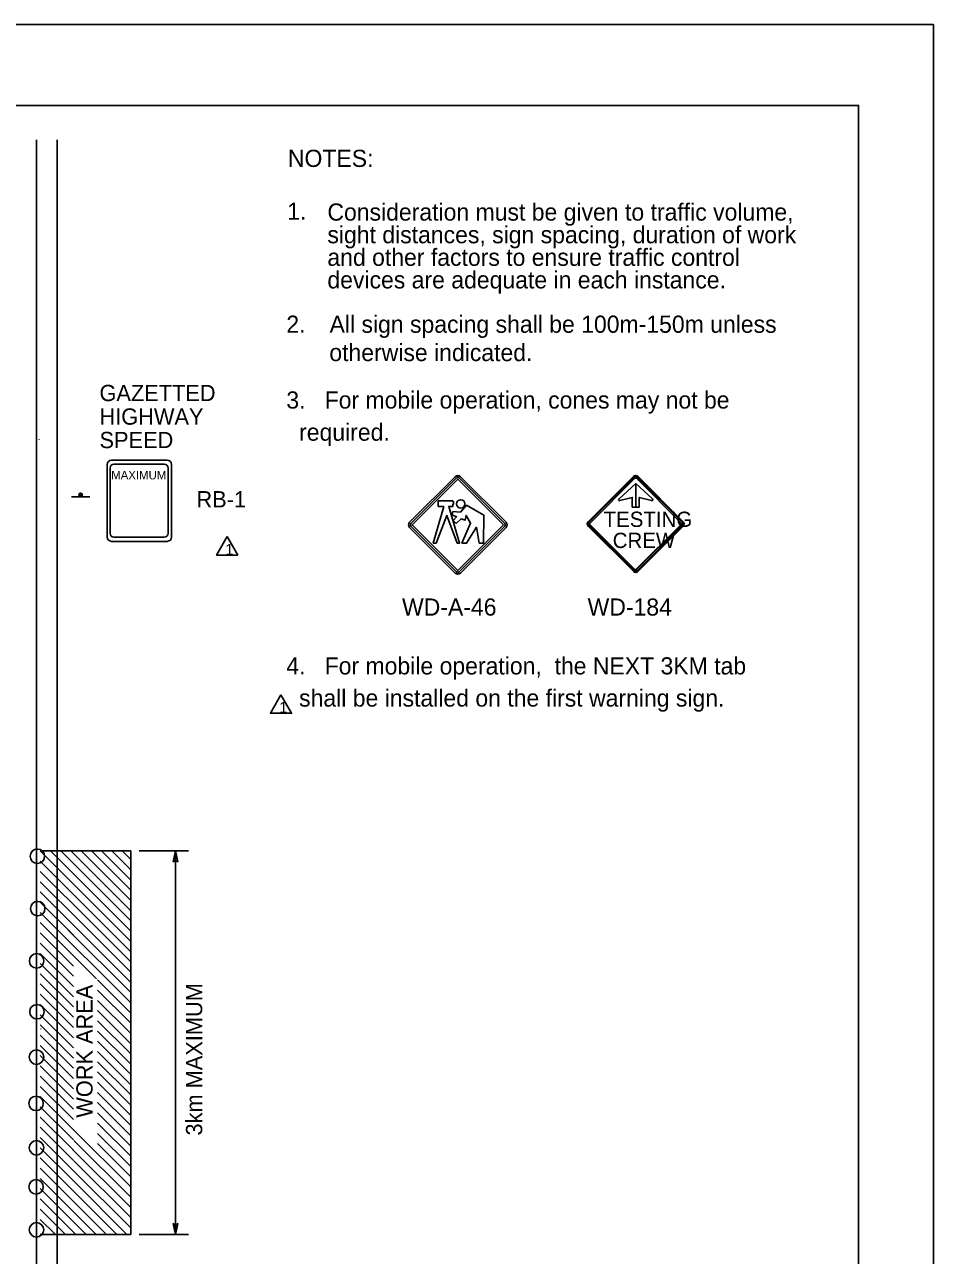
# Model space of a CAD drawing. Extents: x 1371 to 1587, y 163 to 442.
# Drawn here: x 1465.4 to 1587, y 277.8 to 442.4 of the extents above; entities that cross this region are included whole.
import ezdxf

# ---------------------------------------------------------------- set-up
doc = ezdxf.new("R2010")
doc.units = 0
for name, color, linetype in [('Level 1', 7, 'Continuous'), ('Level 10', 7, 'Continuous'), ('Level 2', 7, 'Continuous'), ('Level 3', 7, 'Continuous'), ('Level 44', 7, 'Continuous'), ('Level 60', 7, 'Continuous'), ('Level 61', 7, 'Continuous'), ('Level 62', 7, 'Continuous')]:
    doc.layers.add(name, color=color, linetype=linetype)

msp = doc.modelspace()

# ---------------------------------------------------------------- linework, layer by layer
at = {"layer": 'Level 1'}
for p, q in [((1516.91, 375.86), (1523.01, 381.96)), ((1523.3, 382.27), (1523.3, 382.27)), ((1523.35, 382.3), (1523.35, 382.3)), ((1523.7, 381.96), (1529.8, 375.86)), ((1540.78, 375.93), (1546.87, 382.01)), ((1547.43, 382.01), (1553.51, 375.93)), ((1517.08, 375.69), (1523.18, 381.79)), ((1517.25, 375.52), (1523.35, 381.62)), ((1523.36, 381.62), (1529.46, 375.52)), ((1523.53, 381.79), (1529.63, 375.69)), ((1546.98, 381.9), (1540.89, 375.82)), ((1540.89, 375.82), (1546.98, 381.9)), ((1541, 375.7), (1547.09, 381.79)), ((1547.14, 381.03), (1547.14, 377.9)), ((1547.21, 381.79), (1553.28, 375.7)), ((1523.18, 369.23), (1517.08, 375.34)), ((1523.35, 369.4), (1517.25, 375.51)), ((1523.31, 375.4), (1523.31, 375.4)), ((1529.46, 375.51), (1523.36, 369.4)), ((1529.63, 375.34), (1523.53, 369.23)), ((1540.5, 375.65), (1540.5, 375.65)), ((1546.87, 369.28), (1540.78, 375.36)), ((1547.09, 369.5), (1541, 375.58)), ((1547.17, 369.54), (1553.25, 375.62)), ((1547.17, 369.54), (1553.25, 375.62)), ((1547.17, 369.54), (1553.25, 375.62)), ((1553.25, 375.62), (1547.17, 369.54)), ((1553.28, 375.58), (1547.21, 369.5)), ((1553.51, 375.36), (1547.43, 369.28)), ((1553.79, 375.64), (1553.79, 375.64)), ((1523.01, 369.06), (1516.91, 375.17)), ((1529.8, 375.17), (1523.7, 369.06)), ((1472.72, 330.85), (1472.72, 330.85))]:
    msp.add_line(p, q, dxfattribs=at)
for points in [[(1521.49, 377.99), (1520.74, 377.99), (1520.74, 378.71), (1522.7, 378.71), (1522.7, 378.61), (1522.78, 378.61), (1522.78, 378.32), (1522.7, 378.32), (1522.7, 377.99), (1522.15, 377.99), (1523.59, 373.08), (1523.28, 373.08), (1521.87, 376.79), (1520.46, 373.08), (1520.07, 373.08)], [(1521.49, 377.99), (1520.74, 377.99), (1520.74, 378.71), (1522.7, 378.71), (1522.7, 378.61), (1522.78, 378.61), (1522.78, 378.32), (1522.7, 378.32), (1522.7, 377.99), (1522.15, 377.99), (1523.59, 373.08), (1523.28, 373.08), (1521.87, 376.79), (1520.46, 373.08), (1520.07, 373.08)], [(1522.67, 377.31), (1523.7, 377.22), (1524.52, 378.15), (1526.85, 376.8), (1526.77, 373.08), (1526.22, 373.08), (1525.87, 375.21), (1524.52, 373.08), (1523.9, 373.08), (1525.07, 375.73), (1524.45, 376.79), (1524.33, 376.13), (1523.79, 376.34), (1523.14, 375.72), (1522.74, 376.09), (1523.18, 376.61), (1522.58, 376.88)], [(1522.67, 377.31), (1523.7, 377.22), (1524.52, 378.15), (1526.85, 376.8), (1526.77, 373.08), (1526.22, 373.08), (1525.87, 375.21), (1524.52, 373.08), (1523.9, 373.08), (1525.07, 375.73), (1524.45, 376.79), (1524.33, 376.13), (1523.79, 376.34), (1523.14, 375.72), (1522.74, 376.09), (1523.18, 376.61), (1522.58, 376.88)], [(1492.5, 373.94), (1491.08, 371.47), (1493.92, 371.47)], [(1499.7, 352.8), (1498.28, 350.33), (1501.12, 350.33)]]:
    msp.add_lwpolyline(points, close=True, dxfattribs=at)
for centre, radius, start, end in [((1523.35, 381.61), 0.487, 45.0349, 135), ((1547.15, 381.73), 0.398, 44.9995, 135.0002), ((1547.15, 381.73), 0.241, 44.9995, 135.0002), ((1547.15, 381.73), 0.241, 44.9995, 135.0002), ((1523.35, 381.61), 0.247, 45.0349, 135), ((1523.35, 381.61), 0.00743, 45.0349, 135), ((1547.15, 381.73), 0.0846, 44.9995, 135.0002), ((1547.15, 381.73), 0.0324, 45, 135), ((1547.15, 381.73), 0.0324, 45, 135), ((1547.15, 381.73), 0.0324, 45, 135), ((1517.25, 375.52), 0.487, 135, 224.9651), ((1517.25, 375.52), 0.247, 135, 224.9651), ((1517.25, 375.52), 0.00743, 135, 224.9651), ((1529.46, 375.52), 0.00743, 315, 45.0346), ((1529.46, 375.52), 0.247, 315, 45.0346), ((1529.46, 375.52), 0.487, 315, 45.0346), ((1541.06, 375.64), 0.398, 135.0005, 225), ((1541.06, 375.64), 0.241, 135.0005, 225), ((1541.06, 375.64), 0.241, 135.0005, 225), ((1541.06, 375.64), 0.241, 135.0005, 225), ((1541.06, 375.64), 0.0846, 135.0005, 225), ((1553.23, 375.64), 0.0324, 315, 45), ((1553.23, 375.64), 0.0324, 315, 45), ((1553.23, 375.64), 0.0324, 315, 45), ((1553.23, 375.64), 0.0846, 315.0005, 44.9999), ((1553.23, 375.64), 0.241, 315.0005, 44.9999), ((1553.23, 375.64), 0.241, 315.0005, 44.9999), ((1553.23, 375.64), 0.398, 315.0005, 44.9999), ((1523.35, 369.41), 0.487, 224.965, 315), ((1523.35, 369.41), 0.247, 224.965, 315), ((1523.35, 369.41), 0.00743, 224.965, 315), ((1547.15, 369.56), 0.398, 224.9995, 315), ((1547.15, 369.56), 0.0846, 224.9995, 315), ((1547.15, 369.56), 0.0324, 225, 315), ((1547.15, 369.56), 0.0324, 225, 315), ((1547.15, 369.56), 0.0324, 225, 315)]:
    msp.add_arc(centre, radius, start, end, dxfattribs=at)
at = {"layer": 'Level 10'}
for p, q in [((1467.02, 427.01), (1467.02, 182.32)), ((1469.76, 427.01), (1469.76, 182.32)), ((1467.36, 386.96), (1467.37, 386.95)), ((1467.51, 331.9), (1479.6, 331.9)), ((1467.51, 331.9), (1479.6, 319.8)), ((1467.51, 331.9), (1479.6, 331.9)), ((1468.87, 331.9), (1479.6, 321.17)), ((1470.24, 331.9), (1479.6, 322.54)), ((1471.61, 331.9), (1479.6, 323.91)), ((1472.98, 331.9), (1479.6, 325.28)), ((1474.35, 331.9), (1479.6, 326.64)), ((1475.71, 331.9), (1479.6, 328.01)), ((1477.08, 331.9), (1479.6, 329.38)), ((1478.45, 331.9), (1479.6, 330.75)), ((1479.6, 331.9), (1479.6, 280.61)), ((1480.75, 331.9), (1487.33, 331.9)), ((1485.6, 280.62), (1485.6, 331.9)), ((1467.51, 330.53), (1479.6, 318.43)), ((1467.51, 329.16), (1474.26, 322.41)), ((1467.51, 327.79), (1472.89, 322.41)), ((1467.51, 326.42), (1471.94, 321.99)), ((1467.51, 325.06), (1471.94, 320.62)), ((1467.5, 323.69), (1479.6, 311.59)), ((1467.51, 322.32), (1475.01, 314.81)), ((1471.26, 321.3), (1479.6, 312.96)), ((1471.94, 321.99), (1479.6, 314.33)), ((1472.89, 322.41), (1479.6, 315.7)), ((1474.26, 322.41), (1479.6, 317.06)), ((1467.51, 320.95), (1471.94, 316.51)), ((1467.51, 319.58), (1471.94, 315.14)), ((1467.51, 318.21), (1471.94, 313.78)), ((1467.51, 316.85), (1471.94, 312.41)), ((1467.51, 315.48), (1471.94, 311.04)), ((1475.17, 314.66), (1479.6, 310.22)), ((1467.51, 314.11), (1471.94, 309.67)), ((1475.17, 313.29), (1479.6, 308.85)), ((1467.51, 312.74), (1471.94, 308.3)), ((1467.51, 311.37), (1471.94, 306.93)), ((1475.17, 311.92), (1479.6, 307.49)), ((1467.51, 310), (1471.94, 305.56)), ((1475.17, 310.55), (1479.6, 306.12)), ((1467.51, 308.63), (1471.94, 304.2)), ((1467.58, 308.1), (1467.59, 308.09)), ((1475.17, 309.18), (1479.6, 304.75)), ((1467.51, 307.26), (1471.94, 302.83)), ((1475.17, 307.81), (1479.6, 303.38)), ((1475.17, 306.45), (1479.6, 302.01)), ((1467.51, 305.9), (1471.94, 301.46)), ((1475.17, 305.08), (1479.6, 300.64)), ((1467.51, 304.53), (1471.94, 300.09)), ((1467.51, 303.16), (1471.94, 298.72)), ((1475.17, 303.71), (1479.6, 299.28)), ((1467.51, 301.79), (1471.94, 297.35)), ((1475.17, 302.34), (1479.6, 297.91)), ((1467.51, 300.42), (1471.94, 295.99)), ((1475.17, 300.97), (1479.6, 296.54)), ((1475.17, 299.6), (1479.6, 295.17)), ((1467.51, 299.06), (1471.94, 294.62)), ((1475.17, 298.24), (1479.6, 293.8)), ((1467.51, 297.69), (1471.94, 293.25)), ((1467.51, 296.32), (1471.94, 291.88)), ((1475.17, 296.87), (1479.6, 292.43)), ((1467.51, 294.95), (1471.94, 290.51)), ((1471.9, 294.66), (1479.6, 286.96)), ((1475.17, 295.5), (1479.6, 291.07)), ((1467.51, 293.58), (1471.94, 289.14)), ((1472.02, 293.17), (1479.6, 285.59)), ((1475.17, 294.13), (1479.6, 289.7)), ((1467.51, 292.21), (1471.94, 287.78)), ((1471.87, 291.95), (1479.6, 284.22)), ((1475.17, 292.76), (1479.6, 288.33)), ((1467.51, 290.85), (1477.74, 280.61)), ((1472.01, 290.44), (1479.6, 282.86)), ((1467.51, 289.48), (1476.37, 280.61)), ((1467.51, 288.11), (1475, 280.61)), ((1471.95, 289.13), (1479.6, 281.49)), ((1467.51, 286.74), (1473.63, 280.61)), ((1471.94, 287.78), (1479.1, 280.61)), ((1467.51, 285.37), (1472.26, 280.61)), ((1467.51, 284), (1470.89, 280.61)), ((1467.51, 282.63), (1469.53, 280.61)), ((1467.5, 280.61), (1479.6, 280.61)), ((1480.75, 280.62), (1487.33, 280.62))]:
    msp.add_line(p, q, dxfattribs=at)
for points in [[(1485.6, 331.9), (1485.9, 330.45), (1485.6, 330.69), (1485.3, 330.45)], [(1485.6, 280.62), (1485.3, 282.07), (1485.6, 281.83), (1485.9, 282.07)]]:
    msp.add_lwpolyline(points, close=True, dxfattribs=at)
for centre in [(1467.12, 331.19), (1467.17, 324.19), (1467.02, 317.2), (1467.07, 310.4), (1467, 304.33), (1466.95, 298.14), (1467, 292.2), (1466.95, 286.98), (1467, 281.23)]:
    msp.add_circle(centre, 0.968, dxfattribs=at)
at = {"layer": 'Level 2'}
for centre, radius, start, end in [((1547.15, 381.73), 0.398, 44.9995, 135.0002), ((1547.15, 381.73), 0.241, 44.9995, 135.0002), ((1541.06, 375.64), 0.398, 135.0005, 225), ((1553.23, 375.64), 0.241, 315.0005, 44.9999), ((1553.23, 375.64), 0.398, 315.0005, 44.9999), ((1547.15, 369.56), 0.241, 224.9995, 315)]:
    msp.add_arc(centre, radius, start, end, dxfattribs=at)
at = {"layer": 'Level 3'}
for centre, start, end in [((1547.15, 381.73), 45, 135), ((1547.15, 381.73), 45, 135), ((1553.23, 375.64), 315, 45), ((1553.23, 375.64), 315, 45), ((1547.15, 369.56), 225, 315), ((1547.15, 369.56), 225, 315)]:
    msp.add_arc(centre, 0.0324, start, end, dxfattribs=at)
at = {"layer": 'Level 44'}
for p, q in [((1476.47, 373.89), (1476.47, 383.6)), ((1477.05, 384.18), (1484.5, 384.18)), ((1477.37, 383.64), (1484.08, 383.64)), ((1485.07, 383.6), (1485.07, 373.89)), ((1476.86, 374.38), (1476.86, 383.12)), ((1484.6, 383.12), (1484.6, 374.38)), ((1471.7, 379.25), (1474.12, 379.25)), ((1476.47, 373.89), (1476.47, 373.89)), ((1476.86, 374.38), (1476.86, 374.38)), ((1477.09, 373.81), (1477.09, 373.81)), ((1484.08, 373.87), (1477.37, 373.87)), ((1484.5, 373.31), (1477.05, 373.31)), ((1477.18, 373.56), (1477.18, 373.56))]:
    msp.add_line(p, q, dxfattribs=at)
for centre, radius in [((1472.91, 379.52), 0.242), ((1472.91, 379.52), 0.121), ((1523.74, 378.32), 0.56), ((1523.74, 378.32), 0.56)]:
    msp.add_circle(centre, radius, dxfattribs=at)
for centre, radius, start, end in [((1477.05, 383.6), 0.575, 90, 180), ((1477.37, 383.12), 0.517, 90, 180), ((1484.08, 383.12), 0.517, 360, 90), ((1484.5, 383.6), 0.575, 360, 90), ((1477.05, 373.89), 0.575, 180, 270), ((1477.37, 374.38), 0.517, 180, 270), ((1484.08, 374.38), 0.517, 270, 360), ((1484.5, 373.89), 0.575, 270, 360)]:
    msp.add_arc(centre, radius, start, end, dxfattribs=at)
at = {"layer": 'Level 60'}
msp.add_line((1545.03, 378.76), (1545.03, 378.76), dxfattribs=at)
for points in [[(1370.95, 442.43), (1586.95, 442.43), (1586.95, 163.43), (1370.95, 163.43)], [(1390.08, 431.62), (1576.95, 431.62), (1576.95, 174.24), (1390.08, 174.24)]]:
    msp.add_lwpolyline(points, close=True, dxfattribs=at)
for points in [[(1544.91, 378.99), (1547.14, 381.03), (1549.38, 378.99)], [(1549.25, 378.76), (1547.61, 379.18), (1547.61, 377.9), (1546.68, 377.9), (1546.68, 379.18), (1545.03, 378.76)]]:
    msp.add_lwpolyline(points, dxfattribs=at)
for centre, start, end in [((1545, 378.89), 132.3048, 284.4075), ((1549.29, 378.89), 255.5925, 47.6952)]:
    msp.add_arc(centre, 0.14, start, end, dxfattribs=at)
at = {"layer": 'Level 61'}
msp.add_line((1545.03, 378.76), (1545.03, 378.76), dxfattribs=at)
for points in [[(1544.91, 378.99), (1547.14, 381.03), (1549.38, 378.99)], [(1549.25, 378.76), (1547.61, 379.18), (1547.61, 377.9), (1546.68, 377.9), (1546.68, 379.18), (1545.03, 378.76)]]:
    msp.add_lwpolyline(points, dxfattribs=at)
for centre, start, end in [((1545, 378.89), 132.3048, 284.4075), ((1549.29, 378.89), 255.5925, 47.6952)]:
    msp.add_arc(centre, 0.14, start, end, dxfattribs=at)
at = {"layer": 'Level 62'}
for p, q in [((1540.89, 375.82), (1546.98, 381.9)), ((1547.32, 381.9), (1553.4, 375.82)), ((1545.03, 378.76), (1545.03, 378.76)), ((1546.98, 369.39), (1540.89, 375.47)), ((1553.4, 375.47), (1547.32, 369.39))]:
    msp.add_line(p, q, dxfattribs=at)
for points in [[(1544.91, 378.99), (1547.14, 381.03), (1549.38, 378.99)], [(1549.25, 378.76), (1547.61, 379.18), (1547.61, 377.9), (1546.68, 377.9), (1546.68, 379.18), (1545.03, 378.76)]]:
    msp.add_lwpolyline(points, dxfattribs=at)
for centre, radius, start, end in [((1547.15, 381.73), 0.241, 44.9995, 135.0002), ((1545, 378.89), 0.14, 132.3048, 284.4075), ((1549.29, 378.89), 0.14, 255.5925, 47.6952), ((1541.06, 375.64), 0.241, 135.0005, 225), ((1553.23, 375.64), 0.241, 315.0005, 44.9999), ((1547.15, 369.56), 0.241, 224.9995, 315)]:
    msp.add_arc(centre, radius, start, end, dxfattribs=at)

# ---------------------------------------------------------------- texts
at = {"layer": 'Level 1'}
for p in [(1492.27, 371.53), (1499.48, 350.39)]:
    msp.add_text('1', height=1.45, rotation=360, dxfattribs=at).set_placement(p)
at = {"layer": 'Level 10'}
for s, height, p in [('NOTES:', 2.298, (1500.63, 423.39)), ('1.', 2.298, (1500.54, 416.32)), ('Consideration must be given to traffic volume,', 2.298, (1505.91, 416.21)), ('sight distances, sign spacing, duration of work', 2.298, (1505.91, 413.18)), ('and other factors to ensure traffic control ', 2.298, (1505.91, 410.16)), ('devices are adequate in each instance.', 2.298, (1505.91, 407.14)), ('2.', 2.298, (1500.42, 401.21)), ('All sign spacing shall be 100m-150m unless', 2.298, (1506.2, 401.21)), ('otherwise indicated.', 2.298, (1506.17, 397.42)), ('GAZETTED', 2.177, (1475.43, 392.07)), ('3.   For mobile operation, cones may not be ', 2.298, (1500.42, 391.07)), ('HIGHWAY', 2.177, (1475.43, 388.92)), ('  required.', 2.298, (1500.42, 386.77)), ('SPEED', 2.177, (1475.43, 385.78)), ('WD-A-46', 2.298, (1515.89, 363.38)), ('WD-184', 2.298, (1540.71, 363.38)), ('4.   For mobile operation,  the NEXT 3KM tab ', 2.298, (1500.42, 355.51)), ('  shall be installed on the first warning sign.', 2.298, (1500.42, 351.21))]:
    msp.add_text(s, height=height, dxfattribs=at).set_placement(p)
for s, height, rotation, p in [('RB-1', 2.177, 360, (1488.4, 377.85)), ('WORK AREA', 2.178, 90, (1474.51, 296.22)), ('3km MAXIMUM', 2.1776, 90, (1489.17, 293.84))]:
    msp.add_text(s, height=height, rotation=rotation, dxfattribs=at).set_placement(p)
at = {"layer": 'Level 44'}
msp.add_text('MAXIMUM', height=1.139, rotation=360, dxfattribs=at).set_placement((1477, 381.6))
at = {"layer": 'Level 62'}
for s, p in [('TESTING', (1542.85, 375.24)), ('CREW', (1544.07, 372.42))]:
    msp.add_text(s, height=2.045, rotation=360, dxfattribs=at).set_placement(p)

doc.saveas('drawing.dxf')
